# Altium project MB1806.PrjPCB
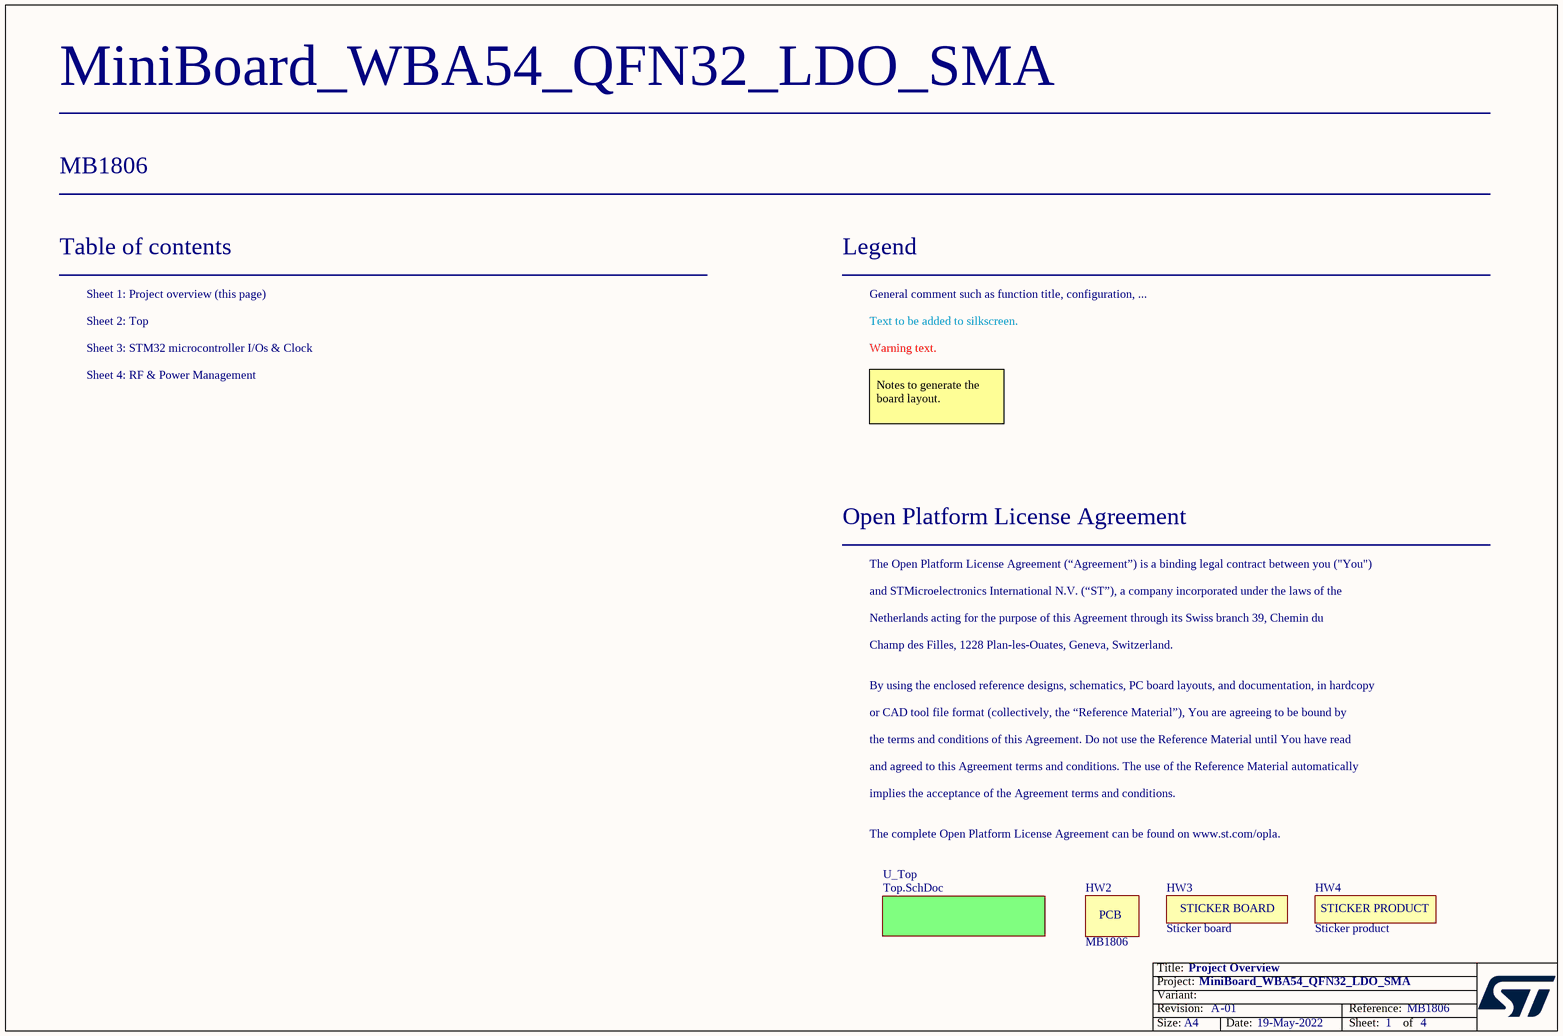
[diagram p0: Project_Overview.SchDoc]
Board_Assembly_Revision: 01; Board_Document_Date: 19-May-2022; Board_Name: MiniBoard_WBA54_QFN32_LDO_SMA; Board_PCB_Revision: A; Board_Reference: MB1806
4 sheets, 81 parts. Net scope: flat (ports and power ports of the same name join across sheets).
Board file: MB1806.PcbDoc
Sheets:
  Project_Overview.SchDoc
    U_Top = Top.SchDoc
      STM32 microcontroller I/Os & Clock = MCU.SchDoc
      RF & Power Management Schematic = RF&Power_Management.SchDoc

## Sheet Project_Overview.SchDoc: Project Overview
size A4; Date: Not used; ApprovedBy: Not used; CheckedBy: Not used; Author: Not used; CompanyName: STMicroelectronics; DrawnBy: Not used; Engineer: Not used; Organization: Not used; Address1: Not used; Address2: Not used; Address3: Not used; Address4: Not used; DocumentNumber: Not used; Revision: Not used; SheetNumber: 1; SheetTotal: 4

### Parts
HW2  value MB1806  (hidden comment: PCB)  (mechanical)
HW3  value Sticker board  [STICKER_BOARD_25X5]  (hidden comment: STICKER_BOARD)  (no BOM)
HW4  value Sticker product  [STICKER_PRODUCT_25X5]  (hidden comment: STICKER_PRODUCT)  (no BOM)

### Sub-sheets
U_Top = Top.SchDoc: no entries

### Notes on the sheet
- Table of contents
- Sheet 1: Project overview (this page)
- Legend
- General comment such as function title, configuration, ...
- Sheet 2: Top
- Sheet 3: STM32 microcontroller I/Os & Clock
- Sheet 4: RF & Power Management
- Text to be added to silkscreen.
- Warning text.
- Notes to generate the board layout.
- Open Platform License Agreement
- The Open Platform License Agreement (“Agreement”) is a binding legal contract between you ("You")
- and STMicroelectronics International N.V. (“ST”), a company incorporated under the laws of the
- Netherlands acting for the purpose of this Agreement through its Swiss branch 39, Chemin du
- Champ des Filles, 1228 Plan-les-Ouates, Geneva, Switzerland.
- By using the enclosed reference designs, schematics, PC board layouts, and documentation, in hardcopy
- or CAD tool file format (collectively, the “Reference Material”), You are agreeing to be bound by
- the terms and conditions of this Agreement. Do not use the Reference Material until You have read
- and agreed to this Agreement terms and conditions. The use of the Reference Material automatically
- implies the acceptance of the Agreement terms and conditions.
- The complete Open Platform License Agreement can be found on www.st.com/opla.

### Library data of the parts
HW2 = MCD-03004: PCB MB1806, 4L2S of MiniBoard for STM32WBA54, QFN32, LDO, SMA.; Part_Preference: Recommended; Manufacturer: PLOTEC; ShowFields: YES; ID: 5120
HW3 = MCD-02190: Sticker board 25x5 mm; Part_Type: Misc; Part_Preference: Recommended
HW4 = MCD-02189: Sticker product 25x5 mm; Part_Type: Misc; Part_Preference: Recommended

## Sheet Top.SchDoc: Top Schematic
size A4; Date: Not used; ApprovedBy: Not used; CheckedBy: Not used; Author: Not used; CompanyName: STMicroelectronics; DrawnBy: Not used; Engineer: Not used; Organization: Not used; Address1: Not used; Address2: Not used; Address3: Not used; Address4: Not used; DocumentNumber: Not used; Revision: Not used; SheetNumber: 2; SheetTotal: 4
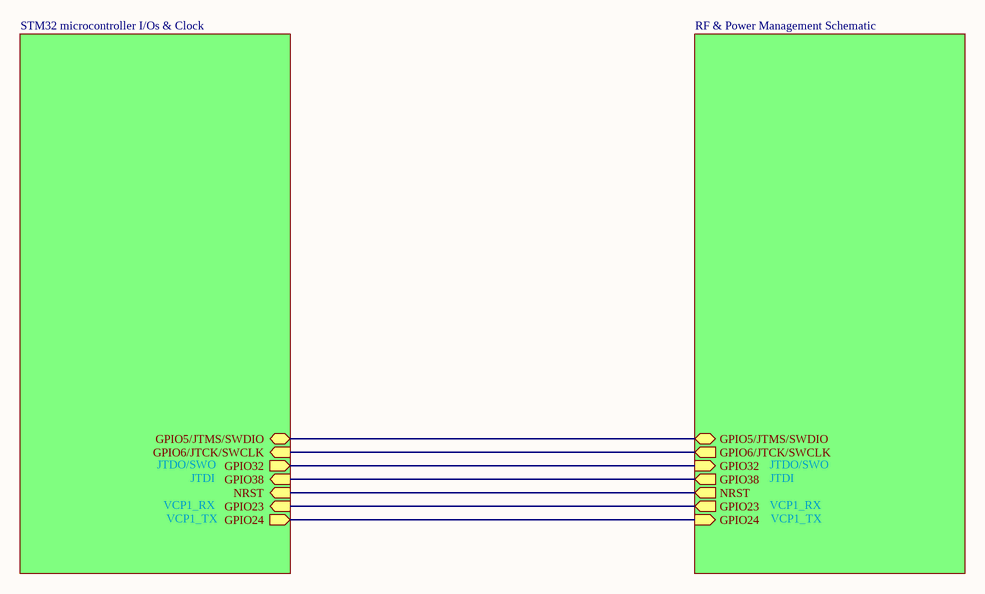
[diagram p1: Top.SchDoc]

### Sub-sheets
RF & Power Management Schematic = RF&Power_Management.SchDoc: GPIO5/JTMS/SWDIO (bidir), GPIO6/JTCK/SWCLK (out), GPIO32 (in), GPIO38 (out), NRST (out), GPIO23 (out), GPIO24 (in)
STM32 microcontroller I/Os & Clock = MCU.SchDoc: GPIO5/JTMS/SWDIO (bidir), GPIO6/JTCK/SWCLK (in), GPIO32 (out), GPIO38 (in), NRST (in), GPIO23 (in), GPIO24 (out)

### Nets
(unnamed): sheet STM32 microcontroller I/Os & Clock/GPIO5/JTMS/SWDIO, sheet RF & Power Management Schematic/GPIO5/JTMS/SWDIO
(unnamed): sheet STM32 microcontroller I/Os & Clock/GPIO6/JTCK/SWCLK, sheet RF & Power Management Schematic/GPIO6/JTCK/SWCLK  [a separate net that carries the same name]
(unnamed): sheet STM32 microcontroller I/Os & Clock/GPIO32, sheet RF & Power Management Schematic/GPIO32  [a separate net that carries the same name]
(unnamed): sheet STM32 microcontroller I/Os & Clock/GPIO38, sheet RF & Power Management Schematic/GPIO38  [a separate net that carries the same name]
(unnamed): sheet STM32 microcontroller I/Os & Clock/NRST, sheet RF & Power Management Schematic/NRST  [a separate net that carries the same name]
(unnamed): sheet STM32 microcontroller I/Os & Clock/GPIO23, sheet RF & Power Management Schematic/GPIO23  [a separate net that carries the same name]
(unnamed): sheet STM32 microcontroller I/Os & Clock/GPIO24, sheet RF & Power Management Schematic/GPIO24  [a separate net that carries the same name]

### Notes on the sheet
- JTDO/SWO
- VCP1_RX
- VCP1_TX
- JTDI

## Sheet MCU.SchDoc: STM32 microcontroller I/Os & Clock
size A4; Date: Not used; ApprovedBy: Not used; CheckedBy: Not used; Author: Not used; CompanyName: STMicroelectronics; DrawnBy: Not used; Engineer: Not used; Organization: Not used; Address1: Not used; Address2: Not used; Address3: Not used; Address4: Not used; DocumentNumber: Not used; Revision: Not used; SheetNumber: 3; SheetTotal: 4
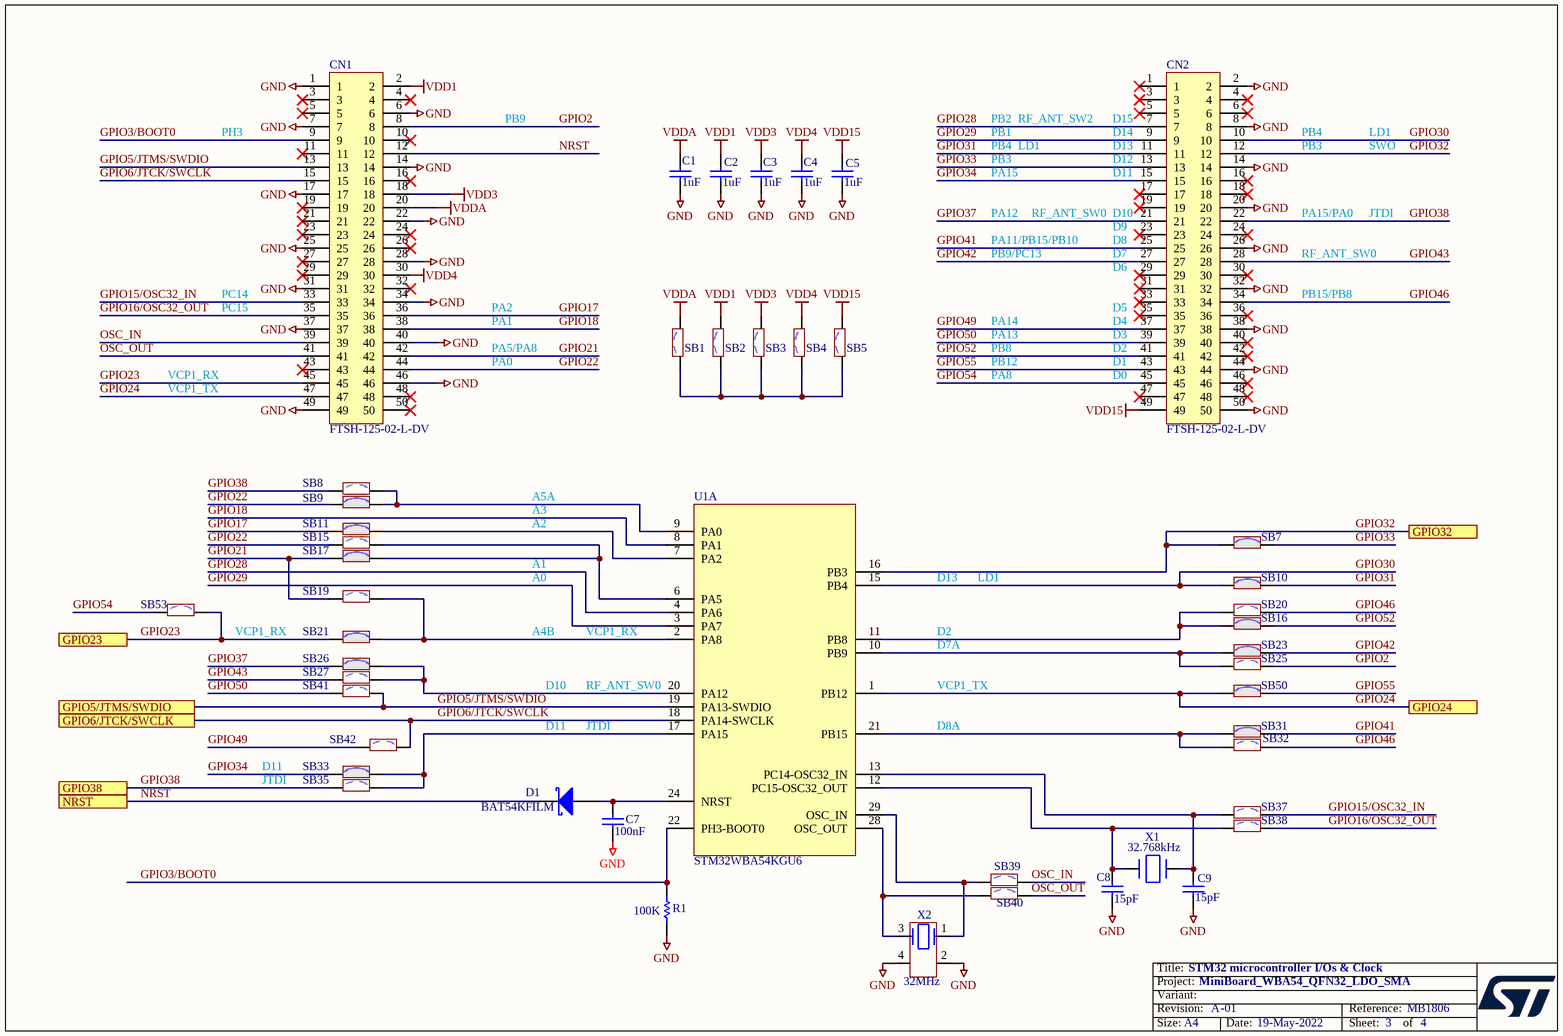
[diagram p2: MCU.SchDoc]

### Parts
C1  value 1uF  [C0402]  (hidden comment: Capacitor)
C2  value 1uF  [C0402]  (hidden comment: Capacitor)
C3  value 1uF  [C0402]  (hidden comment: Capacitor)
C4  value 1uF  [C0402]  (hidden comment: Capacitor)
C5  value 1uF  [C0402]  (hidden comment: Capacitor)
C7  value 100nF  [C0402]  (hidden comment: Capacitor)
C8  value 15pF  [C0402]  (hidden comment: Capacitor)
C9  value 15pF  [C0402]  (hidden comment: Capacitor)
CN1  FTSH-125-02-L-DV  [FTSH-125-02-L-DV]
CN2  FTSH-125-02-L-DV  [FTSH-125-02-L-DV]
D1  value BAT54KFILM  [DIO_SOD523_1A_2K]  (hidden comment: SCHOTTKY_1A_2K)
R1  value 100K  [R0402]  (hidden comment: Resistor)
SB1  SB_OFF  [SOLDER-BRIDGE_R0402-0R]  (value not drawn)
SB2  SB_OFF  [SOLDER-BRIDGE_R0402-0R]  (value not drawn)
SB3  SB_OFF  [SOLDER-BRIDGE_R0402-0R]  (value not drawn)
SB4  SB_OFF  [SOLDER-BRIDGE_R0402-0R]  (value not drawn)
SB5  SB_OFF  [SOLDER-BRIDGE_R0402-0R]  (value not drawn)
SB7  SB_ON  [SOLDER-BRIDGE_R0402-0R]  (value not drawn)
SB8  SB_OFF  [SOLDER-BRIDGE_R0402-0R]  (value not drawn)
SB9  SB_ON  [SOLDER-BRIDGE_R0402-0R]  (value not drawn)
SB10  SB_ON  [SOLDER-BRIDGE_R0402-0R]  (value not drawn)
SB11  SB_ON  [SOLDER-BRIDGE_R0402-0R]  (value not drawn)
SB15  SB_OFF  [SOLDER-BRIDGE_R0402-0R]  (value not drawn)
SB16  SB_ON  [SOLDER-BRIDGE_R0402-0R]  (value not drawn)
SB17  SB_ON  [SOLDER-BRIDGE_R0402-0R]  (value not drawn)
SB19  SB_OFF  [SOLDER-BRIDGE_R0402-0R]  (value not drawn)
SB20  SB_OFF  [SOLDER-BRIDGE_R0402-0R]  (value not drawn)
SB21  SB_ON  [SOLDER-BRIDGE_R0402-0R]  (value not drawn)
SB23  SB_ON  [SOLDER-BRIDGE_R0402-0R]  (value not drawn)
SB25  SB_OFF  [SOLDER-BRIDGE_R0402-0R]  (value not drawn)
SB26  SB_ON  [SOLDER-BRIDGE_R0402-0R]  (value not drawn)
SB27  SB_OFF  [SOLDER-BRIDGE_R0402-0R]  (value not drawn)
SB31  SB_ON  [SOLDER-BRIDGE_R0402-0R]  (value not drawn)
SB32  SB_OFF  [SOLDER-BRIDGE_R0402-0R]  (value not drawn)
SB33  SB_ON  [SOLDER-BRIDGE_R0402-0R]  (value not drawn)
SB35  SB_OFF  [SOLDER-BRIDGE_R0402-0R]  (value not drawn)
SB37  SB_OFF  [SOLDER-BRIDGE_R0402-0R]  (value not drawn)
SB38  SB_OFF  [SOLDER-BRIDGE_R0402-0R]  (value not drawn)
SB39  SB_OFF  [SOLDER-BRIDGE_R0402-0R]  (value not drawn)
SB40  SB_OFF  [SOLDER-BRIDGE_R0402-0R]  (value not drawn)
SB41  SB_OFF  [SOLDER-BRIDGE_R0402-0R]  (value not drawn)
SB42  SB_OFF  [SOLDER-BRIDGE_R0402-0R]  (value not drawn)
SB50  SB_ON  [SOLDER-BRIDGE_R0402-0R]  (value not drawn)
SB53  SB_OFF  [SOLDER-BRIDGE_R0402-0R]  (value not drawn)
U1  STM32WBA54KGU6  [ICC_UFQFPN32-EPAD_5X5_P050]  (part A of 3)
X1  value 32.768kHz  [CRY_NX1610SE_2P]  (hidden comment: XTAL_2_PINS)
X2  value 32MHz  [CRY_NX1612SA_4P]  (hidden comment: XTAL_4_PINS)

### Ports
GPIO5/JTMS/SWDIO, GPIO6/JTCK/SWCLK, GPIO23, GPIO24, GPIO32, GPIO38, NRST

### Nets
GND: C1.1 C2.1 C3.1 C4.1 C5.1 C7.1 C8.1 C9.1 CN1.1 CN1.6 CN1.7 CN1.14 CN1.17 CN1.22 CN1.25 CN1.28 CN1.31 CN1.34 CN1.37 CN1.40 CN1.46 CN1.49 CN2.2 CN2.8 CN2.14 CN2.20 CN2.26 CN2.32 CN2.38 CN2.44 CN2.50 R1.2 X2.2 X2.4
VDD1: C2.2 CN1.2 SB2.2
VDD3: C3.2 CN1.18 SB3.2
VDD4: C4.2 CN1.30 SB4.2
VDD15: C5.2 CN2.49 SB5.2
VDDA: C1.2 CN1.20 SB1.2
GPIO2: CN1.8 SB25.2
GPIO3/BOOT0: CN1.9 R1.1 U1.22(PH3-BOOT0)
GPIO5/JTMS/SWDIO: CN1.13 SB41.2 U1.19(PA13-SWDIO) ; port GPIO5/JTMS/SWDIO
GPIO6/JTCK/SWCLK: CN1.15 SB42.2 U1.18(PA14-SWCLK) ; port GPIO6/JTCK/SWCLK
GPIO15/OSC32_IN: CN1.33 SB37.2
GPIO16/OSC32_OUT: CN1.35 SB38.2
GPIO17: CN1.36 SB11.1
GPIO18: CN1.38 U1.8(PA1)
GPIO21: CN1.42 SB17.1 SB19.1
GPIO22: CN1.44 SB9.1 SB15.1
GPIO23: CN1.45 SB21.1 SB53.2 ; port GPIO23
GPIO24: CN1.47 SB50.1 U1.1(PB12) ; port GPIO24
GPIO28: CN2.7 U1.4(PA6)
GPIO29: CN2.9 U1.3(PA7)
GPIO30: CN2.10 SB10.1 U1.15(PB4)
GPIO31: CN2.11 SB10.2
GPIO32: CN2.12 SB7.1 U1.16(PB3) ; port GPIO32
GPIO33: CN2.13 SB7.2
GPIO34: CN2.15 SB33.1
GPIO37: CN2.21 SB26.1
GPIO38: CN2.22 SB8.1 SB35.1 ; port GPIO38
GPIO41: CN2.25 SB31.2
GPIO42: CN2.27 SB23.2
GPIO43: CN2.28 SB27.1
GPIO46: CN2.34 SB20.2 SB32.2
GPIO49: CN2.37 SB42.1
GPIO50: CN2.39 SB41.1
GPIO52: CN2.41 SB16.2
GPIO54: CN2.45 SB53.1
GPIO55: CN2.43 SB50.2
NRST: CN1.12 D1.2(K) ; port NRST
OSC_IN: CN1.39 SB39.2
OSC_OUT: CN1.41 SB40.2
NetC7_2: C7.2 D1.1(A) U1.24(NRST)
NetC8_2: C8.2 SB38.1 U1.12(PC15-OSC32_OUT) X1.2(X2)
NetC9_2: C9.2 SB37.1 U1.13(PC14-OSC32_IN) X1.1(X1)
NetSB1_1: SB1.1 SB2.1 SB3.1 SB4.1 SB5.1
NetSB8_2: SB8.2 SB9.2 U1.9(PA0)
NetSB11_2: SB11.2 U1.7(PA2)
NetSB15_2: SB15.2 SB17.2 U1.6(PA5)
NetSB16_1: SB16.1 SB20.1 U1.11(PB8)
NetSB19_2: SB19.2 SB21.2 U1.2(PA8)
NetSB23_1: SB23.1 SB25.1 U1.10(PB9)
NetSB26_2: SB26.2 SB27.2 U1.20(PA12)
NetSB31_1: SB31.1 SB32.1 U1.21(PB15)
NetSB33_2: SB33.2 SB35.2 U1.17(PA15)
NetSB39_1: SB39.1 U1.29(OSC_IN) X2.1
NetSB40_1: SB40.1 U1.28(OSC_OUT) X2.3

Not connected (* = marked no-connect by the designer): CN1 3* 4* 5* 10* 11* 16* 19* 21* 23* 24* 26* 27* 29* 32* 43* 48* 50*; CN2 1* 3* 4* 5* 6* 16* 17* 18* 19* 23* 24* 29* 30* 31* 33* 35* 36* 40* 42* 46* 47* 48*

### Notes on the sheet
- PH3
- PB9
- PB1
- PB2
- PB3
- PB4
- PA15
- LD1
- RF_ANT_SW2
- (near CN2) D11
- (near CN2) D13
- (near CN2) D14
- (near CN2) D15
- (near CN2) D12
- SWO
- PA11/PB15/PB10
- PA12
- RF_ANT_SW0
- (near CN2) D10
- (near CN2) D9
- (near CN2) D8
- PA15/PA0
- JTDI
- PC14
- PC15
- PA2
- PB9/PC13
- (near CN2) D7
- (near CN2) D6
- (near CN2) D5
- PB15/PB8
- VCP1_RX
- PA0
- PA5/PA8
- PA1
- PA14
- PA8
- PB12
- PA13
- PB8
- (near CN2) D1
- (near CN2) D4
- (near CN2) D3
- (near CN2) D2
- (near CN2) D0
- VCP1_TX
- A3
- A5A
- A0
- A2
- A1
- D13
- A4B
- D7A
- D2
- D10
- (near U1) RF_ANT_SW0
- D11
- D8A

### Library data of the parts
C1-C5 = MCD-01722: Capacitor, MLCC, 1uF, 10V, X5R, +/-10%, 0402, T=0.5mm; Part_Preference: Recommended; Manufacturer: YAGEO; Manufacturer_Part_Number: CC0402KRX5R6BB105; Component_Country_Of_Origin: China
C7 = MCD-00006: Capacitor, MLCC, 100nF, 16V, X7R, +/-10%, 0402, T=0.5mm; Manufacturer_Part_Number: CC0402KRX7R7BB104; Manufacturer: YAGEO; Alternate_Manufacturer_Part_Number: GCM155R71C104KA55D; Alternate_Manufacturer: MURATA; Part_Preference: Recommended; Order_Code_RS: 616-9701
C8 C9 = MCD-01933: Capacitor, MLCC, 15pF, 50V, NPO, +/-2%, 0402, T=0.5mm; Part_Preference: Recommended; Manufacturer: YAGEO; Manufacturer_Part_Number: CC0402GRNPO9BN150; Component_Country_Of_Origin: China
CN1 CN2 = MCD-02746: Header, 25x2, 12.7mm, VR, SMD, T=4.83mm; Part_Type: Connector; Part_Preference: Recommended; Manufacturer: SAMTEC; Value: Header 25x2; Component_Country_Of_Origin: China, Costa Rica, Malaysia, USA, Vietnam; ShowFields: YES; ID: 4858
D1 = MCD-01677: Small signal Schottky diodes; Part_Type: Diode; Manufacturer: STMICROELECTRONICS; BMS_Part_Number: 9151123; Part_Preference: Recommended; Manufacturer_HQ_COO: EU
R1 = MCD-00059: Resistor, 100K, 0402, +/-1%, 1/16W; Part_Preference: Recommended; Manufacturer: YAGEO; Manufacturer_Part_Number: RC0402FR-07100KL; Component_Country_Of_Origin: China
SB1-SB5 SB8 SB15 SB19 SB20 SB25 SB27 SB32 SB35 SB37-SB42 SB53 = MCD-02162: Solder Bridge 0402 OFF; Part_Type: Misc; Part_Preference: Recommended; Manufacturer: YAGEO; Manufacturer_Part_Number: RC0402JR-070RL; Order_Code_RS: 618-5804; Component_Country_Of_Origin: China
SB7 SB9-SB11 SB16 SB17 SB21 SB23 SB26 SB31 SB33 SB50 = MCD-01618: Solder Bridge 0402 ON; Part_Type: Misc; Part_Preference: Recommended; Manufacturer: YAGEO; Manufacturer_Part_Number: RC0402JR-070RL; Order_Code_RS: 618-5804; Component_Country_Of_Origin: China
U1 = MCD-02744: MCU, ARM Cortex-M33 32-bit, 1MB Flash, 128KB SRAM, With Crypto; Part_Type: IC; Part_Preference: Recommended; Manufacturer: STMICROELECTRONICS; Order_Code_RS: 151-764; Component_Country_Of_Origin: China; ShowFields: YES; ID: 4856
X1 = MCD-02579: Crystal, 32.768kHz, 6pF, +/-20ppm, 70KR, 1.6x1mm; Part_Type: Crystal_Osc; Part_Preference: Recommended; Manufacturer: NDK; Manufacturer_Part_Number: NX1610SE-32.768KHZ-EXS00A-MU01501
X2 = MCD-02578: Crystal, 32MHz, 8pF, +/-10ppm, 40R, 1612(metric), T=0.3mm; Part_Type: Crystal_Osc; Part_Preference: Recommended; Manufacturer: NDK; Manufacturer_Part_Number: NX1612SA-32MHZ-EXS00A-CS09166

## Sheet RF&Power_Management.SchDoc: RF & Power Management Schematic
size A4; Date: Not used; ApprovedBy: Not used; CheckedBy: Not used; Author: Not used; CompanyName: STMicroelectronics; DrawnBy: Not used; Engineer: Not used; Organization: Not used; Address1: Not used; Address2: Not used; Address3: Not used; Address4: Not used; DocumentNumber: Not used; Revision: Not used; SheetNumber: 4; SheetTotal: 4
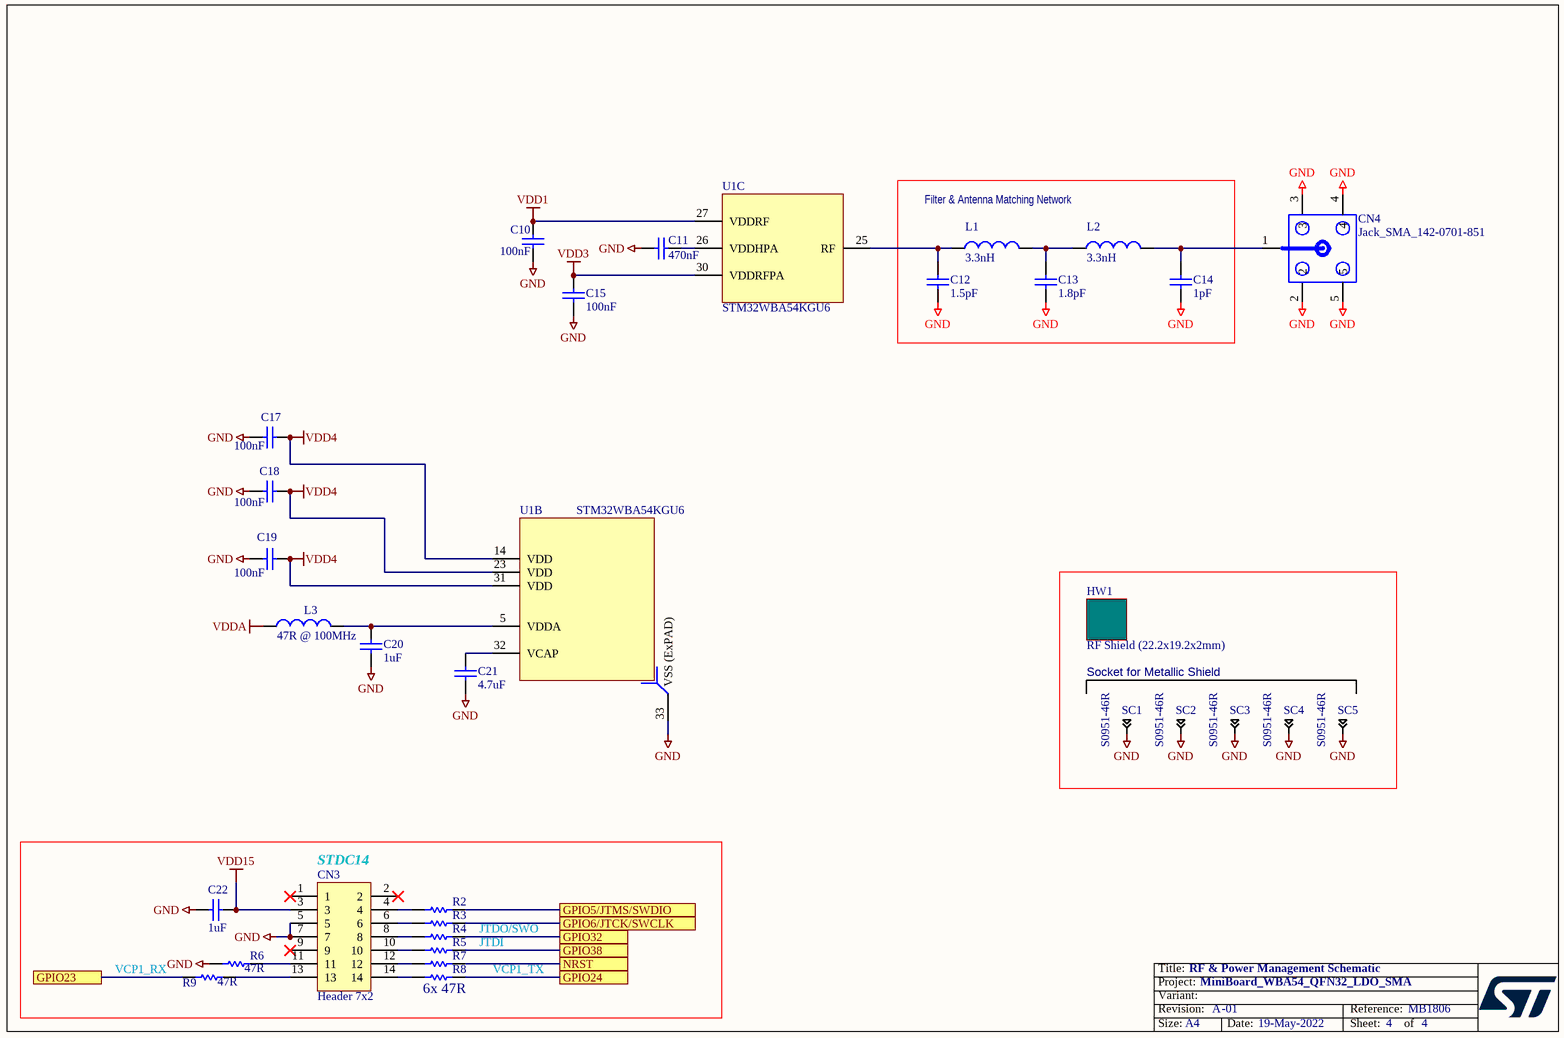
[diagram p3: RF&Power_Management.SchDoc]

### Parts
C10  value 100nF  [C0402]  (hidden comment: Capacitor)
C11  value 470nF  [C0603]  (hidden comment: Capacitor)
C12  value 1.5pF  [C0402]  (hidden comment: Capacitor)
C13  value 1.8pF  [C0402]  (hidden comment: Capacitor)
C14  value 1pF  [C0402]  (hidden comment: Capacitor)
C15  value 100nF  [C0402]  (hidden comment: Capacitor)
C17  value 100nF  [C0402]  (hidden comment: Capacitor)
C18  value 100nF  [C0402]  (hidden comment: Capacitor)
C19  value 100nF  [C0402]  (hidden comment: Capacitor)
C20  value 1uF  [C0402]  (hidden comment: Capacitor)
C21  value 4.7uF  [C0603_H0P8]  (hidden comment: Capacitor)
C22  value 1uF  [C0603]  (hidden comment: Capacitor)
CN3  Header 7x2  [CON_SAMTEC_FTSH-107-01-L-DV-K-A]
CN4  value Jack_SMA_142-0701-851  [CON_SMA-RF_CINCH_142-0701-851]  (hidden comment: SMA-J-P-H-ST-EM1)
HW1  RF Shield (22.2x19.2x2mm)  [SHIELD_RF_ST-CUSTOM_22P2X19P2_H2]
L1  value 3.3nH  [C0402]  (hidden comment: Inductor)
L2  value 3.3nH  [C0402]  (hidden comment: Inductor)
L3  value 47R @ 100MHz  [IND_0603_H0P8]  (hidden comment: Inductor)
R2  Resistor  [R0402]  (value not drawn)
R3  Resistor  [R0402]  (value not drawn)
R4  Resistor  [R0402]  (value not drawn)
R5  Resistor  [R0402]  (value not drawn)
R6  value 47R  [R0402]  (hidden comment: Resistor)
R7  Resistor  [R0402]  (value not drawn)
R8  Resistor  [R0402]  (value not drawn)
R9  value 47R  [R0402]  (hidden comment: Resistor)
SC1  value S0951-46R  [CLIP_HARWIN_S0951-46R]  (hidden comment: Shield-clip_S0951-46R)
SC2  value S0951-46R  [CLIP_HARWIN_S0951-46R]  (hidden comment: Shield-clip_S0951-46R)
SC3  value S0951-46R  [CLIP_HARWIN_S0951-46R]  (hidden comment: Shield-clip_S0951-46R)
SC4  value S0951-46R  [CLIP_HARWIN_S0951-46R]  (hidden comment: Shield-clip_S0951-46R)
SC5  value S0951-46R  [CLIP_HARWIN_S0951-46R]  (hidden comment: Shield-clip_S0951-46R)
U1  STM32WBA54KGU6  [ICC_UFQFPN32-EPAD_5X5_P050]  (parts B,C of 3)

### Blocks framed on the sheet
Filter & Antenna Matching Network: C12-C14 L1 L2
Socket for Metallic Shield: HW1 SC1-SC5

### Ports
GPIO5/JTMS/SWDIO, GPIO6/JTCK/SWCLK, GPIO23, GPIO24, GPIO32, GPIO38, NRST

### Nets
GND: C10.2 C11.1 C12.1 C13.1 C14.1 C15.2 C17.2 C18.2 C19.2 C20.1 C21.1 C22.1 CN3.5 CN3.7 CN4.2 CN4.3 CN4.4 CN4.5 R6.1 SC1.1 SC2.1 SC3.1 SC4.1 SC5.1 U1.33(VSS_(ExPAD))
VDD1: C10.1 U1.27(VDDRF)
VDD3: C15.1 U1.30(VDDRFPA)
VDD4: C17.1 C18.1 C19.1 U1.14(VDD) U1.23(VDD) U1.31(VDD)
VDD15: C22.2 CN3.3
VDDA: L3.1
GPIO5/JTMS/SWDIO: R2.2 ; port GPIO5/JTMS/SWDIO
GPIO6/JTCK/SWCLK: R3.2 ; port GPIO6/JTCK/SWCLK
GPIO23: R9.1 ; port GPIO23
GPIO24: R8.2 ; port GPIO24
GPIO32: R4.2 ; port GPIO32
GPIO38: R5.2 ; port GPIO38
NRST: R7.2 ; port NRST
NetC11_2: C11.2 U1.26(VDDHPA)
NetC12_2: C12.2 L1.1 U1.25(RF)
NetC13_2: C13.2 L1.2 L2.1
NetC14_2: C14.2 CN4.1 L2.2
NetC20_2: C20.2 L3.2 U1.5(VDDA)
NetC21_2: C21.2 U1.32(VCAP)
NetCN3_4: CN3.4 R2.1
NetCN3_6: CN3.6 R3.1
NetCN3_8: CN3.8 R4.1
NetCN3_10: CN3.10 R5.1
NetCN3_11: CN3.11 R6.2
NetCN3_12: CN3.12 R7.1
NetCN3_13: CN3.13 R9.2
NetCN3_14: CN3.14 R8.1

Not connected (* = marked no-connect by the designer): CN3 1* 2* 9*

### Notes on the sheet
- (near CN3) STDC14
- (near R9) VCP1_RX
- JTDI
- JTDO/SWO
- VCP1_TX
- (near R8) 6x 47R

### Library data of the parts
C10 C15 C17-C19 = MCD-00006: as C7 on sheet MCU
C11 = MCD-01006: Capacitor, MLCC, 470nF, 16V, X7R, +/-10%, 0603, T=0.8mm; BMS_Part_Number: 9142003; Part_Preference: Recommended; Manufacturer: YAGEO; Manufacturer_Part_Number: CC0603KRX7R7BB474; Order_Code_RS: 200-6576; Component_Country_Of_Origin: China
C12 = MCD-02994: Capacitor, MLCC, 1.5pF, 50V, C0G, +/-0.25pF, 0402, T=0.5mm; Part_Preference: Recommended; Manufacturer: MURATA; Manufacturer_Part_Number: GRM1555C1H1R5CA01; Component_Country_Of_Origin: Japan°; ShowFields: YES; ID: 5110
C13 = MCD-02995: Capacitor, MLCC, 1.8pF, 50V, C0G, +/-0.25pF, 0402, T=0.5mm; Part_Preference: Recommended; Manufacturer: MURATA; Manufacturer_Part_Number: GRM1555C1H1R8CA01; Order_Code_RS: 723-5357; Component_Country_Of_Origin: Japan°; ShowFields: YES; ID: 5111
C14 = MCD-03045: Capacitor, MLCC, 1.0pF, 50V, C0G, +/-0.25pF, 0402, T=0.5mm; Part_Preference: Recommended; Manufacturer: MURATA; Manufacturer_Part_Number: GRM1555C1H1R0CA01; ShowFields: YES; ID: 5161
C20 = MCD-01722: as C1 on sheet MCU
C21 = MCD-01721: Capacitor, MLCC, 4.7uF, 10V, X5R, +/-10%, 0603, T=0.8mm; Part_Preference: Recommended; Manufacturer: YAGEO; Manufacturer_Part_Number: CC0603KRX5R6BB475; Component_Country_Of_Origin: China
C22 = MCD-00010: Capacitor, MLCC, 1uF, 16V, X5R, 10%, 0603, T=0,8mm; Manufacturer_Part_Number: CC0603KRX5R7BB105; Manufacturer: YAGEO; Provided_By: Subcon; Initial_Board_Reference: MB1274
CN3 = MCD-01531: Header, 7x2, 1.27mm, VR, T=5.97mm, FTSH series STDC14 without Alignment Pin; Part_Type: Connector; Part_Preference: Recommended; Manufacturer: SAMTEC; Manufacturer_Part_Number: FTSH-107-01-L-DV-K; Order_Code_RS: 179-9021; Component_Country_Of_Origin: China, Costa Rica, Malaysia, United States, Vietnam
CN4 = MCD-02072: Jack_SMA, VR, PCB edge, 50R, T=7.92mm; Part_Type: Connector; Part_Preference: Recommended; Manufacturer: JOHNSON; Manufacturer_Part_Number: 142-0701-851; Order_Code_RS: 885-7532; Component_Country_Of_Origin: United States; ShowFields: YES; ID: 4172
HW1 = MCD-03256: Part_Type: Misc; Part_Preference: Recommended; Manufacturer: TBD; ShowFields: YES; ID: 5372
L1 L2 = MCD-03001: Inductor, 3.3nH, +/-0.3nH, 800 mA, 0.125Ohm, 0402, T=0.5mm; Part_Preference: Recommended; Manufacturer: MURATA; Manufacturer_Part_Number: LQG15HS3N3S02; Component_Country_Of_Origin: Japan°; ShowFields: YES; ID: 5117
L3 = MCD-02587: Ferrite bead, 47R @ 100MHz, +/-25%, 3.5A, 0R02, 0603, T=0.8mm; Part_Preference: Recommended; Manufacturer: TAIYO YUDEN; Manufacturer_Part_Number: FBMH1608HM470-T
R2-R9 = MCD-00481: Resistor,47R,0402,1%,1/16W; Manufacturer_Part_Number: RC0402FR-0747RL; Manufacturer: YAGEO; Provided_By: Subcon
SC1-SC5 = MCD-01587: shield clip Harwin S0951-46R to fix RF shielded cavity; Part_Type: Misc; Part_Preference: Recommended; Component_Country_Of_Origin: South Korea
U1 = MCD-02744: as U1 on sheet MCU

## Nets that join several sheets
GND: MCU (34 pins), RF&Power_Management (25 pins)
VDD1: MCU (C2.2 CN1.2 SB2.2), RF&Power_Management (C10.1 U1.27)
VDD3: MCU (C3.2 CN1.18 SB3.2), RF&Power_Management (C15.1 U1.30)
VDD4: MCU (C4.2 CN1.30 SB4.2), RF&Power_Management (6 pins)
VDD15: MCU (C5.2 CN2.49 SB5.2), RF&Power_Management (C22.2 CN3.3)
VDDA: MCU (C1.2 CN1.20 SB1.2), RF&Power_Management (L3.1)
GPIO5/JTMS/SWDIO: MCU (CN1.13 SB41.2 U1.19), RF&Power_Management (R2.2)
GPIO6/JTCK/SWCLK: MCU (CN1.15 SB42.2 U1.18), RF&Power_Management (R3.2)
GPIO23: MCU (CN1.45 SB21.1 SB53.2), RF&Power_Management (R9.1)
GPIO24: MCU (CN1.47 SB50.1 U1.1), RF&Power_Management (R8.2)
GPIO32: MCU (CN2.12 SB7.1 U1.16), RF&Power_Management (R4.2)
GPIO38: MCU (CN2.22 SB8.1 SB35.1), RF&Power_Management (R5.2)
NRST: MCU (CN1.12 D1.2), RF&Power_Management (R7.2)

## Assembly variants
WBA54KGB: not fitted C1 C2 C3 C4 C5 C22 CN3 R2 R3 R4 R5 R6 R7 R8 R9 SB1 SB2 SB3 SB4 SB5 SB8 SB15 SB19 SB20 SB25 SB27 SB32 SB35 SB37 SB38 SB39 SB40 SB41 SB42 SB53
